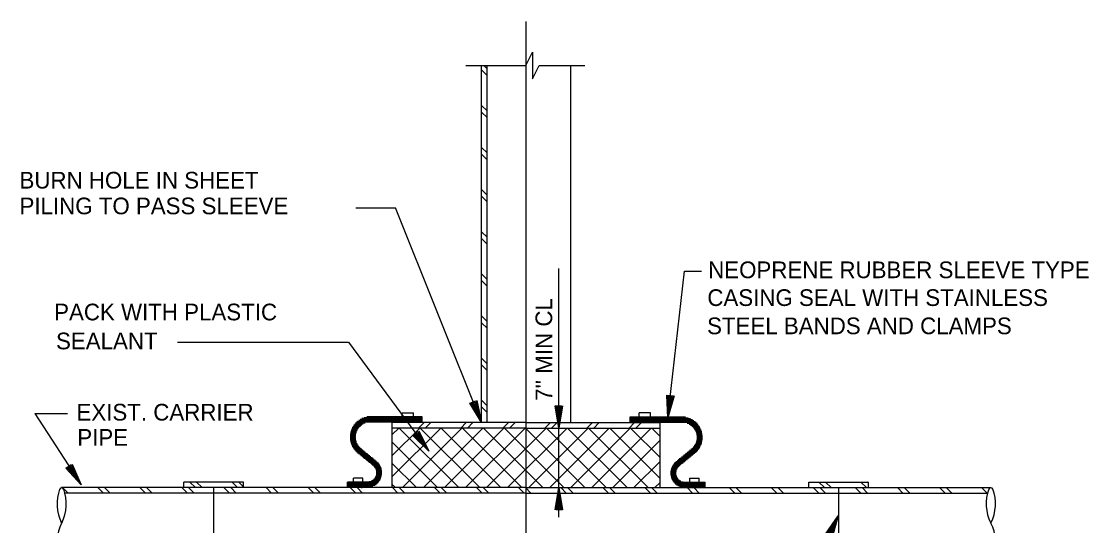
# Model space of a CAD drawing. Extents: x 22411.4 to 22495.4, y 22369.6 to 22415.
# Drawn here: x 22450.89 to 22462.85, y 22388.98 to 22394.63 of the extents above; entities that cross this region are included whole.
import ezdxf

# ---------------------------------------------------------------- set-up
doc = ezdxf.new("R2010")
doc.units = 0
for name, color, linetype in [('Level 1', 7, 'Continuous'), ('Level 2', 7, 'Continuous'), ('Level 4', 7, 'Continuous'), ('Level 8', 7, 'Continuous')]:
    doc.layers.add(name, color=color, linetype=linetype)

msp = doc.modelspace()

# ---------------------------------------------------------------- linework, layer by layer
at = {"layer": 'Level 1'}
for p, q in [((22456.549, 22385.383), (22456.549, 22394.627)), ((22455.873, 22394.132), (22456.545, 22394.132)), ((22456.695, 22394.132), (22457.204, 22394.132)), ((22456.914, 22390.075), (22456.914, 22391.86)), ((22455.158, 22390.2), (22455.158, 22390.247)), ((22455.158, 22390.247), (22455.286, 22390.247)), ((22455.286, 22390.2), (22455.286, 22390.247)), ((22457.813, 22390.2), (22457.813, 22390.247)), ((22457.941, 22390.247), (22457.813, 22390.247)), ((22457.941, 22390.2), (22457.941, 22390.247)), ((22458.144, 22390.261), (22458.144, 22390.261)), ((22456.024, 22390.202), (22456.024, 22390.202)), ((22456.049, 22390.138), (22456.049, 22390.138)), ((22458.136, 22390.192), (22458.136, 22390.192)), ((22456.914, 22389.409), (22456.914, 22390.075)), ((22455.419, 22389.874), (22455.419, 22389.874)), ((22455.46, 22389.818), (22455.46, 22389.818)), ((22454.614, 22389.471), (22454.614, 22389.514)), ((22454.718, 22389.514), (22454.614, 22389.514)), ((22454.718, 22389.471), (22454.718, 22389.514)), ((22458.381, 22389.471), (22458.381, 22389.514)), ((22458.381, 22389.514), (22458.485, 22389.514)), ((22458.485, 22389.471), (22458.485, 22389.514)), ((22451.526, 22389.5), (22451.526, 22389.5)), ((22451.564, 22389.442), (22451.564, 22389.442)), ((22456.914, 22389.078), (22456.914, 22389.409)), ((22460.014, 22389.032), (22460.014, 22389.032)), ((22460.044, 22389.095), (22460.044, 22389.095))]:
    msp.add_line(p, q, dxfattribs=at)
for points in [[(22456.545, 22394.132), (22456.62, 22394.282), (22456.62, 22393.982), (22456.695, 22394.132)], [(22456.955, 22390.325), (22456.914, 22390.075), (22456.873, 22390.325), (22456.943, 22390.325), (22456.914, 22390.145), (22456.886, 22390.314), (22456.931, 22390.314), (22456.914, 22390.211), (22456.899, 22390.303), (22456.918, 22390.303), (22456.914, 22390.281)], [(22456.873, 22389.159), (22456.914, 22389.409), (22456.955, 22389.159), (22456.885, 22389.159), (22456.914, 22389.339), (22456.942, 22389.17), (22456.897, 22389.17), (22456.914, 22389.273), (22456.929, 22389.181), (22456.91, 22389.181), (22456.914, 22389.203)], [(22460.383, 22389.461), (22460.373, 22389.471)]]:
    msp.add_lwpolyline(points, dxfattribs=at)
for centre, radius, start, end in [((22451.774, 22389.228), 0.48, 159.8064, 206.6071), ((22451.346, 22389.385), 0.0235, 20.1936, 159.8064), ((22450.918, 22389.228), 0.48, 333.3929, 20.1936), ((22462.181, 22389.228), 0.48, 159.8064, 206.6071), ((22461.753, 22389.385), 0.0235, 20.1936, 159.8064), ((22461.325, 22389.228), 0.48, 333.3929, 20.1936), ((22451.774, 22388.798), 0.48, 153.3929, 200.1919), ((22461.325, 22388.798), 0.48, 339.8081, 26.6071)]:
    msp.add_arc(centre, radius, start, end, dxfattribs=at)
at = {"layer": 'Level 2'}
for p, q in [((22456.049, 22390.138), (22456.049, 22394.132)), ((22456.112, 22390.138), (22456.112, 22394.132)), ((22457.049, 22390.138), (22457.049, 22394.132)), ((22454.642, 22392.54), (22455.084, 22392.54)), ((22456.049, 22390.138), (22455.084, 22392.54)), ((22458.136, 22390.192), (22458.322, 22391.832)), ((22458.322, 22391.832), (22458.511, 22391.832)), ((22452.643, 22391.038), (22454.56, 22391.038)), ((22454.56, 22391.038), (22455.46, 22389.818)), ((22451.044, 22390.239), (22451.413, 22390.239)), ((22451.044, 22390.239), (22451.564, 22389.442)), ((22455.384, 22390.2), (22454.765, 22390.2)), ((22456.549, 22390.138), (22455.049, 22390.138)), ((22455.049, 22389.409), (22455.049, 22390.138)), ((22455.384, 22390.138), (22455.384, 22390.2)), ((22456.549, 22390.138), (22458.049, 22390.138)), ((22457.715, 22390.2), (22458.334, 22390.2)), ((22457.715, 22390.138), (22457.715, 22390.2)), ((22458.049, 22389.409), (22458.049, 22390.138)), ((22456.549, 22390.075), (22455.049, 22390.075)), ((22456.549, 22390.075), (22458.049, 22390.075)), ((22456.549, 22389.409), (22451.346, 22389.409)), ((22452.716, 22389.409), (22452.716, 22389.471)), ((22453.383, 22389.471), (22452.716, 22389.471)), ((22453.049, 22388.617), (22453.049, 22389.409)), ((22453.383, 22389.409), (22453.383, 22389.471)), ((22454.811, 22389.471), (22454.546, 22389.471)), ((22454.546, 22389.409), (22454.546, 22389.471)), ((22454.707, 22389.404), (22454.707, 22389.408)), ((22456.549, 22389.409), (22461.753, 22389.409)), ((22458.288, 22389.471), (22458.553, 22389.471)), ((22458.553, 22389.409), (22458.553, 22389.471)), ((22459.716, 22389.409), (22459.716, 22389.471)), ((22459.716, 22389.471), (22460.383, 22389.471)), ((22460.049, 22388.617), (22460.049, 22389.409)), ((22460.383, 22389.409), (22460.383, 22389.471)), ((22456.549, 22389.346), (22451.385, 22389.346)), ((22456.549, 22389.346), (22461.714, 22389.346)), ((22456.549, 22389.204), (22456.549, 22389.204)), ((22459.039, 22386.96), (22460.044, 22389.095)), ((22456.549, 22389.013), (22456.549, 22389.013))]:
    msp.add_line(p, q, dxfattribs=at)
for points in [[(22455.995, 22390.385), (22456.049, 22390.138), (22455.918, 22390.354), (22455.984, 22390.38), (22456.024, 22390.202), (22455.934, 22390.349), (22455.977, 22390.366), (22455.999, 22390.264), (22455.951, 22390.344), (22455.968, 22390.351), (22455.973, 22390.328)], [(22458.206, 22390.435), (22458.136, 22390.192), (22458.123, 22390.445), (22458.194, 22390.437), (22458.144, 22390.261), (22458.135, 22390.433), (22458.18, 22390.427), (22458.152, 22390.327), (22458.147, 22390.42), (22458.166, 22390.418), (22458.16, 22390.396)], [(22454.708, 22390.109), (22454.62, 22390.109)], [(22454.724, 22390.119), (22454.628, 22390.119)], [(22454.747, 22390.13), (22454.637, 22390.13)], [(22455.383, 22390.14), (22454.647, 22390.14)], [(22455.383, 22390.151), (22454.659, 22390.151)], [(22455.383, 22390.161), (22454.673, 22390.161)], [(22455.383, 22390.171), (22454.689, 22390.171)], [(22455.383, 22390.182), (22454.709, 22390.182)], [(22455.383, 22390.192), (22454.736, 22390.192)], [(22457.716, 22390.192), (22458.363, 22390.192)], [(22457.716, 22390.182), (22458.39, 22390.182)], [(22457.716, 22390.171), (22458.41, 22390.171)], [(22457.716, 22390.161), (22458.426, 22390.161)], [(22457.716, 22390.151), (22458.44, 22390.151)], [(22457.716, 22390.14), (22458.451, 22390.14)], [(22458.352, 22390.13), (22458.462, 22390.13)], [(22458.375, 22390.119), (22458.471, 22390.119)], [(22458.391, 22390.109), (22458.479, 22390.109)], [(22454.639, 22389.994), (22454.577, 22389.994)], [(22454.641, 22390.005), (22454.578, 22390.005)], [(22454.643, 22390.015), (22454.58, 22390.015)], [(22454.647, 22390.026), (22454.582, 22390.026)], [(22454.65, 22390.036), (22454.584, 22390.036)], [(22454.655, 22390.046), (22454.588, 22390.046)], [(22454.66, 22390.057), (22454.591, 22390.057)], [(22454.667, 22390.067), (22454.596, 22390.067)], [(22454.675, 22390.078), (22454.601, 22390.078)], [(22454.684, 22390.088), (22454.606, 22390.088)], [(22454.695, 22390.098), (22454.613, 22390.098)], [(22455.345, 22390.043), (22455.46, 22389.818), (22455.279, 22389.994), (22455.335, 22390.036), (22455.419, 22389.874), (22455.296, 22389.993), (22455.332, 22390.02), (22455.379, 22389.927), (22455.313, 22389.993), (22455.328, 22390.004), (22455.338, 22389.983)], [(22458.404, 22390.098), (22458.486, 22390.098)], [(22458.415, 22390.088), (22458.493, 22390.088)], [(22458.424, 22390.078), (22458.498, 22390.078)], [(22458.432, 22390.067), (22458.503, 22390.067)], [(22458.438, 22390.057), (22458.508, 22390.057)], [(22458.444, 22390.046), (22458.511, 22390.046)], [(22458.449, 22390.036), (22458.515, 22390.036)], [(22458.452, 22390.026), (22458.517, 22390.026)], [(22458.455, 22390.015), (22458.519, 22390.015)], [(22458.458, 22390.005), (22458.521, 22390.005)], [(22458.459, 22389.994), (22458.522, 22389.994)], [(22454.639, 22389.984), (22454.576, 22389.984)], [(22454.638, 22389.973), (22454.576, 22389.973)], [(22454.639, 22389.963), (22454.576, 22389.963)], [(22454.64, 22389.953), (22454.577, 22389.953)], [(22454.641, 22389.942), (22454.578, 22389.942)], [(22454.644, 22389.932), (22454.58, 22389.932)], [(22454.647, 22389.921), (22454.582, 22389.921)], [(22454.65, 22389.911), (22454.584, 22389.911)], [(22454.655, 22389.901), (22454.588, 22389.901)], [(22454.661, 22389.89), (22454.591, 22389.89)], [(22454.667, 22389.88), (22454.596, 22389.88)], [(22454.675, 22389.869), (22454.601, 22389.869)], [(22458.424, 22389.869), (22458.498, 22389.869)], [(22458.432, 22389.88), (22458.503, 22389.88)], [(22458.438, 22389.89), (22458.507, 22389.89)], [(22458.444, 22389.901), (22458.511, 22389.901)], [(22458.449, 22389.911), (22458.515, 22389.911)], [(22458.452, 22389.921), (22458.517, 22389.921)], [(22458.455, 22389.932), (22458.519, 22389.932)], [(22458.458, 22389.942), (22458.521, 22389.942)], [(22458.459, 22389.953), (22458.522, 22389.953)], [(22458.46, 22389.984), (22458.523, 22389.984)], [(22458.46, 22389.963), (22458.523, 22389.963)], [(22458.461, 22389.973), (22458.523, 22389.973)], [(22454.684, 22389.859), (22454.606, 22389.859)], [(22454.695, 22389.848), (22454.613, 22389.848)], [(22454.707, 22389.838), (22454.62, 22389.838)], [(22454.72, 22389.828), (22454.628, 22389.828)], [(22454.733, 22389.817), (22454.637, 22389.817)], [(22454.746, 22389.807), (22454.648, 22389.807)], [(22454.758, 22389.796), (22454.66, 22389.796)], [(22454.771, 22389.786), (22454.672, 22389.786)], [(22454.784, 22389.776), (22454.685, 22389.776)], [(22454.797, 22389.765), (22454.698, 22389.765)], [(22454.809, 22389.755), (22454.711, 22389.755)], [(22458.289, 22389.755), (22458.388, 22389.755)], [(22458.302, 22389.765), (22458.401, 22389.765)], [(22458.315, 22389.776), (22458.414, 22389.776)], [(22458.328, 22389.786), (22458.427, 22389.786)], [(22458.341, 22389.796), (22458.439, 22389.796)], [(22458.353, 22389.807), (22458.451, 22389.807)], [(22458.366, 22389.817), (22458.462, 22389.817)], [(22458.379, 22389.828), (22458.471, 22389.828)], [(22458.392, 22389.838), (22458.479, 22389.838)], [(22458.404, 22389.848), (22458.486, 22389.848)], [(22458.415, 22389.859), (22458.492, 22389.859)], [(22451.462, 22389.673), (22451.564, 22389.442), (22451.393, 22389.628), (22451.452, 22389.667), (22451.526, 22389.5), (22451.41, 22389.627), (22451.448, 22389.651), (22451.49, 22389.556), (22451.427, 22389.625), (22451.443, 22389.635), (22451.452, 22389.614)], [(22454.822, 22389.744), (22454.723, 22389.744)], [(22454.835, 22389.734), (22454.736, 22389.734)], [(22454.848, 22389.723), (22454.749, 22389.723)], [(22454.86, 22389.713), (22454.762, 22389.713)], [(22454.873, 22389.703), (22454.774, 22389.703)], [(22454.885, 22389.692), (22454.787, 22389.692)], [(22454.894, 22389.682), (22454.8, 22389.682)], [(22454.902, 22389.671), (22454.813, 22389.671)], [(22454.909, 22389.661), (22454.825, 22389.661)], [(22454.915, 22389.651), (22454.838, 22389.651)], [(22454.92, 22389.64), (22454.847, 22389.64)], [(22454.924, 22389.63), (22454.855, 22389.63)], [(22458.175, 22389.63), (22458.244, 22389.63)], [(22458.179, 22389.64), (22458.251, 22389.64)], [(22458.184, 22389.651), (22458.261, 22389.651)], [(22458.19, 22389.661), (22458.273, 22389.661)], [(22458.197, 22389.671), (22458.286, 22389.671)], [(22458.205, 22389.682), (22458.299, 22389.682)], [(22458.214, 22389.692), (22458.312, 22389.692)], [(22458.226, 22389.703), (22458.325, 22389.703)], [(22458.238, 22389.713), (22458.337, 22389.713)], [(22458.251, 22389.723), (22458.35, 22389.723)], [(22458.264, 22389.734), (22458.363, 22389.734)], [(22458.277, 22389.744), (22458.376, 22389.744)], [(22454.922, 22389.515), (22454.852, 22389.515)], [(22454.925, 22389.526), (22454.858, 22389.526)], [(22454.927, 22389.619), (22454.86, 22389.619)], [(22454.928, 22389.536), (22454.863, 22389.536)], [(22454.929, 22389.609), (22454.865, 22389.609)], [(22454.93, 22389.546), (22454.867, 22389.546)], [(22454.931, 22389.598), (22454.868, 22389.598)], [(22454.932, 22389.557), (22454.869, 22389.557)], [(22454.932, 22389.588), (22454.87, 22389.588)], [(22454.933, 22389.578), (22454.87, 22389.578)], [(22454.933, 22389.567), (22454.87, 22389.567)], [(22458.166, 22389.588), (22458.229, 22389.588)], [(22458.166, 22389.578), (22458.228, 22389.578)], [(22458.166, 22389.567), (22458.229, 22389.567)], [(22458.167, 22389.557), (22458.23, 22389.557)], [(22458.168, 22389.598), (22458.231, 22389.598)], [(22458.168, 22389.546), (22458.232, 22389.546)], [(22458.169, 22389.609), (22458.234, 22389.609)], [(22458.171, 22389.536), (22458.236, 22389.536)], [(22458.172, 22389.619), (22458.238, 22389.619)], [(22458.173, 22389.526), (22458.241, 22389.526)], [(22458.177, 22389.515), (22458.247, 22389.515)], [(22454.89, 22389.463), (22454.549, 22389.463)], [(22454.88, 22389.453), (22454.549, 22389.453)], [(22454.867, 22389.442), (22454.549, 22389.442)], [(22454.852, 22389.432), (22454.549, 22389.432)], [(22454.831, 22389.421), (22454.549, 22389.421)], [(22454.797, 22389.411), (22454.549, 22389.411)], [(22454.899, 22389.473), (22454.79, 22389.473)], [(22454.906, 22389.484), (22454.817, 22389.484)], [(22454.912, 22389.494), (22454.832, 22389.494)], [(22454.917, 22389.505), (22454.843, 22389.505)], [(22458.181, 22389.505), (22458.256, 22389.505)], [(22458.187, 22389.494), (22458.266, 22389.494)], [(22458.193, 22389.484), (22458.282, 22389.484)], [(22458.2, 22389.473), (22458.308, 22389.473)], [(22458.209, 22389.463), (22458.549, 22389.463)], [(22458.219, 22389.453), (22458.549, 22389.453)], [(22458.232, 22389.442), (22458.549, 22389.442)], [(22458.247, 22389.432), (22458.549, 22389.432)], [(22458.267, 22389.421), (22458.549, 22389.421)], [(22458.302, 22389.411), (22458.549, 22389.411)], [(22459.9, 22388.887), (22460.044, 22389.095), (22459.975, 22388.852), (22459.911, 22388.882), (22460.014, 22389.032), (22459.967, 22388.867), (22459.926, 22388.886), (22459.986, 22388.972), (22459.96, 22388.882), (22459.943, 22388.89), (22459.956, 22388.909)]]:
    msp.add_lwpolyline(points, dxfattribs=at)
at = {"layer": 'Level 8'}
for points in [[(22456.112, 22394.021), (22456.049, 22394.083)], [(22456.112, 22394.096), (22456.076, 22394.132)], [(22456.112, 22393.625), (22456.049, 22393.687)], [(22456.112, 22393.55), (22456.049, 22393.612)], [(22456.112, 22393.154), (22456.049, 22393.216)], [(22456.112, 22393.078), (22456.049, 22393.141)], [(22456.112, 22392.682), (22456.049, 22392.745)], [(22456.112, 22392.607), (22456.049, 22392.669)], [(22456.112, 22392.211), (22456.049, 22392.273)], [(22456.112, 22392.135), (22456.049, 22392.198)], [(22456.112, 22391.739), (22456.049, 22391.802)], [(22456.112, 22391.664), (22456.049, 22391.726)], [(22456.112, 22391.268), (22456.049, 22391.33)], [(22456.112, 22391.192), (22456.049, 22391.255)], [(22456.112, 22390.796), (22456.049, 22390.859)], [(22456.112, 22390.721), (22456.049, 22390.784)], [(22456.112, 22390.325), (22456.049, 22390.388)], [(22456.112, 22390.25), (22456.049, 22390.312)], [(22455.344, 22390.075), (22455.406, 22390.138)], [(22455.419, 22390.075), (22455.482, 22390.138)], [(22455.815, 22390.075), (22455.877, 22390.138)], [(22455.89, 22390.075), (22455.953, 22390.138)], [(22456.286, 22390.075), (22456.349, 22390.138)], [(22456.362, 22390.075), (22456.424, 22390.138)], [(22456.758, 22390.075), (22456.82, 22390.138)], [(22456.833, 22390.075), (22456.896, 22390.138)], [(22457.229, 22390.075), (22457.292, 22390.138)], [(22457.305, 22390.075), (22457.367, 22390.138)], [(22457.701, 22390.075), (22457.763, 22390.138)], [(22457.776, 22390.075), (22457.839, 22390.138)], [(22455.049, 22389.532), (22455.593, 22390.075)], [(22455.049, 22389.767), (22455.358, 22390.075)], [(22455.049, 22390.003), (22455.122, 22390.075)], [(22455.793, 22389.409), (22455.126, 22390.075)], [(22455.162, 22389.409), (22455.829, 22390.075)], [(22456.029, 22389.409), (22455.362, 22390.075)], [(22455.398, 22389.409), (22456.065, 22390.075)], [(22456.265, 22389.409), (22455.598, 22390.075)], [(22455.634, 22389.409), (22456.3, 22390.075)], [(22456.5, 22389.409), (22455.834, 22390.075)], [(22455.87, 22389.409), (22456.536, 22390.075)], [(22456.736, 22389.409), (22456.069, 22390.075)], [(22456.105, 22389.409), (22456.772, 22390.075)], [(22456.972, 22389.409), (22456.305, 22390.075)], [(22456.341, 22389.409), (22457.008, 22390.075)], [(22457.207, 22389.409), (22456.541, 22390.075)], [(22456.577, 22389.409), (22457.243, 22390.075)], [(22457.443, 22389.409), (22456.776, 22390.075)], [(22456.812, 22389.409), (22457.479, 22390.075)], [(22457.679, 22389.409), (22457.012, 22390.075)], [(22457.048, 22389.409), (22457.715, 22390.075)], [(22457.914, 22389.409), (22457.248, 22390.075)], [(22457.284, 22389.409), (22457.95, 22390.075)], [(22458.049, 22389.51), (22457.484, 22390.075)], [(22458.049, 22389.745), (22457.719, 22390.075)], [(22458.049, 22389.981), (22457.955, 22390.075)], [(22455.557, 22389.409), (22455.049, 22389.917)], [(22457.519, 22389.409), (22458.049, 22389.939)], [(22455.322, 22389.409), (22455.049, 22389.681)], [(22457.755, 22389.409), (22458.049, 22389.703)], [(22451.417, 22389.346), (22451.354, 22389.409)], [(22451.813, 22389.346), (22451.75, 22389.409)], [(22451.888, 22389.346), (22451.826, 22389.409)], [(22452.284, 22389.346), (22452.222, 22389.409)], [(22452.359, 22389.346), (22452.297, 22389.409)], [(22452.755, 22389.346), (22452.693, 22389.409)], [(22452.831, 22389.346), (22452.768, 22389.409)], [(22452.845, 22389.409), (22452.782, 22389.471)], [(22452.92, 22389.409), (22452.858, 22389.471)], [(22453.227, 22389.346), (22453.164, 22389.409)], [(22453.302, 22389.346), (22453.24, 22389.409)], [(22453.316, 22389.409), (22453.254, 22389.471)], [(22453.383, 22389.418), (22453.329, 22389.471)], [(22453.698, 22389.346), (22453.636, 22389.409)], [(22453.774, 22389.346), (22453.711, 22389.409)], [(22454.17, 22389.346), (22454.107, 22389.409)], [(22454.245, 22389.346), (22454.183, 22389.409)], [(22454.641, 22389.346), (22454.579, 22389.409)], [(22454.716, 22389.346), (22454.654, 22389.409)], [(22455.086, 22389.409), (22455.049, 22389.445)], [(22455.112, 22389.346), (22455.05, 22389.409)], [(22455.188, 22389.346), (22455.125, 22389.409)], [(22455.584, 22389.346), (22455.521, 22389.409)], [(22455.659, 22389.346), (22455.597, 22389.409)], [(22456.055, 22389.346), (22455.993, 22389.409)], [(22456.131, 22389.346), (22456.068, 22389.409)], [(22456.527, 22389.346), (22456.464, 22389.409)], [(22456.602, 22389.346), (22456.54, 22389.409)], [(22456.998, 22389.346), (22456.936, 22389.409)], [(22457.074, 22389.346), (22457.011, 22389.409)], [(22457.469, 22389.346), (22457.407, 22389.409)], [(22457.545, 22389.346), (22457.482, 22389.409)], [(22457.941, 22389.346), (22457.878, 22389.409)], [(22458.016, 22389.346), (22457.954, 22389.409)], [(22457.991, 22389.409), (22458.049, 22389.467)], [(22458.412, 22389.346), (22458.35, 22389.409)], [(22458.488, 22389.346), (22458.425, 22389.409)], [(22458.884, 22389.346), (22458.821, 22389.409)], [(22458.959, 22389.346), (22458.897, 22389.409)], [(22459.355, 22389.346), (22459.293, 22389.409)], [(22459.431, 22389.346), (22459.368, 22389.409)], [(22459.827, 22389.346), (22459.764, 22389.409)], [(22459.889, 22389.409), (22459.826, 22389.471)], [(22459.902, 22389.346), (22459.839, 22389.409)], [(22459.964, 22389.409), (22459.902, 22389.471)], [(22460.298, 22389.346), (22460.235, 22389.409)], [(22460.36, 22389.409), (22460.298, 22389.471)], [(22460.373, 22389.346), (22460.311, 22389.409)], [(22460.769, 22389.346), (22460.707, 22389.409)], [(22460.845, 22389.346), (22460.782, 22389.409)], [(22461.241, 22389.346), (22461.178, 22389.409)], [(22461.316, 22389.346), (22461.254, 22389.409)], [(22461.712, 22389.346), (22461.65, 22389.409)]]:
    msp.add_lwpolyline(points, dxfattribs=at)

# ---------------------------------------------------------------- texts
at = {"layer": 'Level 4'}
for s, height, p in [('BURN HOLE IN SHEET', 0.18667, (22450.874, 22392.756)), ('PILING TO PASS SLEEVE', 0.18667, (22450.874, 22392.468)), ('NEOPRENE RUBBER SLEEVE TYPE', 0.18667, (22458.587, 22391.753)), ('CASING SEAL WITH STAINLESS', 0.18667, (22458.578, 22391.442)), ('PACK WITH PLASTIC', 0.18667, (22451.262, 22391.281)), ('STEEL BANDS AND CLAMPS', 0.18667, (22458.575, 22391.126)), ('SEALANT', 0.1867, (22451.283, 22390.957)), ('EXIST. CARRIER', 0.18667, (22451.512, 22390.16)), ('PIPE', 0.1867, (22451.521, 22389.878))]:
    msp.add_text(s, height=height, dxfattribs=at).set_placement(p)
msp.add_text("7'' MIN CL", height=0.1867, rotation=90, dxfattribs=at).set_placement((22456.84, 22390.38))

doc.saveas('drawing.dxf')
